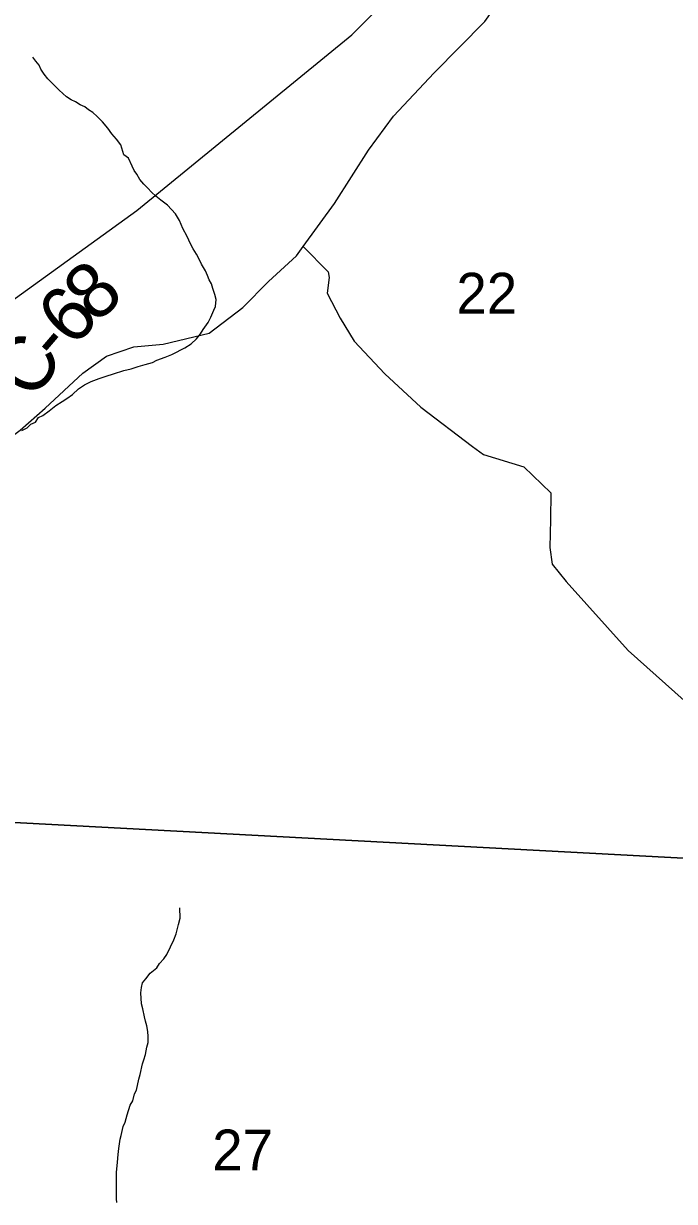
# Model space of a CAD drawing. Extents: x 0 to 34, y 0 to 22.
# Drawn here: x 5.915 to 6.583, y 16.581 to 17.789 of the extents above; entities that cross this region are included whole.
import ezdxf

# ---------------------------------------------------------------- set-up
doc = ezdxf.new("R2010")
doc.units = 0
for name, color, linetype in [('GM_P_State_Alignment', 7, 'Continuous'), ('GM_X_County_Road', 7, 'Continuous'), ('GM_X_County_Road_Text', 7, 'Continuous'), ('GM_X_Minor_River', 7, 'Continuous'), ('GM_X_Section', 7, 'Continuous'), ('GM_X_Section_Text', 7, 'Continuous'), ('GM_X_Township_ROW', 7, 'Continuous'), ('SH_Data', 7, 'Continuous')]:
    doc.layers.add(name, color=color, linetype=linetype)

msp = doc.modelspace()

# ---------------------------------------------------------------- linework, layer by layer
at = {"layer": 'GM_P_State_Alignment'}
msp.add_lwpolyline([(5.7539, 17.3702), (5.755, 17.3719), (5.7846, 17.4188), (6.0315, 17.5972), (6.2517, 17.7771), (6.3812, 17.906), (6.3923, 17.9142), (6.5211, 17.9881), (6.5265, 17.9911), (6.5405, 17.99), (6.6417, 17.9816), (6.6804, 17.9677), (6.7928, 17.9227), (6.8111, 17.9139), (6.95, 17.8445), (6.9564, 17.8413), (6.9734, 17.8302), (7.1338, 17.7232), (7.4175, 17.6454), (7.7316, 17.5623), (7.9253, 17.5014), (8.1533, 17.4614), (8.4655, 17.4165), (8.5004, 17.4073)], dxfattribs=at)
at = {"layer": 'GM_X_County_Road'}
msp.add_lwpolyline([(5.8626, 17.3148), (5.864, 17.3177), (5.8632, 17.3276), (5.8651, 17.3344), (5.8738, 17.3436), (5.9117, 17.3717), (5.9375, 17.3945), (5.9761, 17.4302), (6.0004, 17.4477), (6.0284, 17.4572), (6.0584, 17.4599), (6.1057, 17.4713), (6.1402, 17.4976), (6.1663, 17.5242), (6.1951, 17.5504), (6.2021, 17.56), (6.2341, 17.6043), (6.269, 17.659), (6.2947, 17.6936), (6.3364, 17.7381), (6.3883, 17.7909), (6.4224, 17.8395), (6.444, 17.868), (6.4684, 17.8891)], dxfattribs=at)
at = {"layer": 'GM_X_Minor_River'}
for points in [[(6.0016, 17.6814), (5.9961, 17.688), (5.9908, 17.6934), (5.9864, 17.6976), (5.9819, 17.7004), (5.9781, 17.7035), (5.9733, 17.7055), (5.9684, 17.7086), (5.9639, 17.7106), (5.9594, 17.7137), (5.9519, 17.7203), (5.9475, 17.7245), (5.94, 17.7322), (5.9363, 17.7369), (5.933, 17.7419), (5.9312, 17.7461), (5.9278, 17.7503), (5.9249, 17.7541)], [(5.9136, 17.3716), (5.919, 17.3742), (5.9228, 17.3779), (5.9274, 17.3801), (5.9305, 17.3846), (5.9351, 17.3868), (5.9416, 17.3917), (5.9485, 17.3969), (5.9547, 17.401), (5.9597, 17.4043), (5.9654, 17.4084), (5.9716, 17.414), (5.9777, 17.4184), (5.9846, 17.4217), (5.9926, 17.4246), (5.9998, 17.4272), (6.0074, 17.4297), (6.0181, 17.433), (6.0257, 17.4347), (6.0326, 17.4369), (6.0398, 17.4391), (6.0474, 17.4412), (6.052, 17.4434), (6.0604, 17.4467), (6.0673, 17.4492), (6.0722, 17.4518), (6.0764, 17.454), (6.0806, 17.4562), (6.0871, 17.4603), (6.0925, 17.4655), (6.0968, 17.4704), (6.0995, 17.4749), (6.1046, 17.4821), (6.1073, 17.4877), (6.1105, 17.4949), (6.1121, 17.4987), (6.1126, 17.5059), (6.1115, 17.5108), (6.1093, 17.517), (6.1079, 17.5219), (6.1057, 17.5258), (6.1039, 17.5304), (6.1017, 17.5353), (6.0977, 17.5419), (6.0955, 17.5465), (6.0925, 17.5522), (6.0892, 17.5576), (6.0863, 17.563), (6.083, 17.5702), (6.0786, 17.5787), (6.0753, 17.5867), (6.0709, 17.5936), (6.0627, 17.6025), (6.056, 17.6075), (6.0508, 17.6118), (6.0463, 17.6157), (6.0426, 17.6199), (6.0385, 17.6242), (6.0344, 17.6288), (6.0315, 17.6342), (6.0285, 17.638), (6.0267, 17.6426), (6.0227, 17.6507), (6.0182, 17.6542), (6.015, 17.6645), (6.0105, 17.6703), (6.0057, 17.6757), (6.0016, 17.6814)], [(6.0108, 16.5798), (6.0105, 16.5836), (6.0104, 16.5977), (6.0106, 16.6106), (6.0116, 16.6213), (6.0121, 16.6289), (6.0129, 16.6353), (6.0142, 16.6448), (6.0154, 16.6486), (6.0175, 16.6577), (6.0195, 16.6622), (6.0215, 16.6698), (6.0247, 16.6796), (6.0274, 16.6841), (6.0291, 16.6913), (6.031, 16.6951), (6.0335, 16.7061), (6.0347, 16.711), (6.0372, 16.722), (6.0384, 16.7262), (6.0404, 16.7315), (6.0416, 16.739), (6.0429, 16.744), (6.043, 16.75), (6.0427, 16.755), (6.0416, 16.7611), (6.0402, 16.7657), (6.0391, 16.7703), (6.0374, 16.7783), (6.036, 16.7836), (6.0354, 16.7947), (6.0363, 16.8004), (6.0371, 16.8049), (6.0406, 16.809), (6.0452, 16.815), (6.0518, 16.8203), (6.0545, 16.8248), (6.0591, 16.8296), (6.0622, 16.8341), (6.0658, 16.8421), (6.0693, 16.8492), (6.0717, 16.8553), (6.0741, 16.8647), (6.0758, 16.8712), (6.0756, 16.8818)]]:
    msp.add_lwpolyline(points, dxfattribs=at)
at = {"layer": 'GM_X_Section'}
msp.add_lwpolyline([(5.784, 17.9889), (6.8533, 17.9287), (6.7904, 16.9223), (5.726, 16.9791)], close=True, dxfattribs=at)
msp.add_lwpolyline([(5.726, 16.9791), (6.7904, 16.9223), (6.7682, 16.601), (6.755, 16.5938), (6.7273, 16.5816), (6.68, 16.5577)], dxfattribs=at)
at = {"layer": 'GM_X_Township_ROW'}
msp.add_lwpolyline([(6.2021, 17.56), (6.2277, 17.5343), (6.2285, 17.5283), (6.2265, 17.5123), (6.2397, 17.4866), (6.2541, 17.4629), (6.2857, 17.4295), (6.3226, 17.3954), (6.3755, 17.3551), (6.387, 17.3469), (6.4282, 17.3342), (6.4559, 17.3076), (6.4555, 17.2802), (6.4547, 17.2513), (6.4574, 17.2342), (6.4715, 17.2166), (6.5351, 17.146), (6.6531, 17.0404), (6.7536, 17.0209), (6.7741, 17.0166), (6.7839, 17.0124), (6.7902, 17.0069), (6.8013, 16.9946)], dxfattribs=at)
at = {"layer": 'SH_Data'}
msp.add_lwpolyline([(5.7846, 17.4188), (6.0315, 17.5972), (6.2517, 17.7771), (6.3812, 17.906), (6.5265, 17.9911), (6.6417, 17.9816), (6.7928, 17.9227), (6.95, 17.8445), (7.1338, 17.7232), (7.4175, 17.6454), (7.7316, 17.5623), (7.9253, 17.5014)], dxfattribs=at)

# ---------------------------------------------------------------- texts
at = {"layer": 'GM_X_County_Road_Text'}
for s, rotation, p in [('8', 42.8202, (5.9893, 17.4801)), ('6', 45.9858, (5.9656, 17.4555)), ('C', 57.4988, (5.9271, 17.4008)), ('-', 49.2844, (5.9509, 17.4385))]:
    msp.add_text(s, height=0.0568, rotation=rotation, dxfattribs=at).set_placement(p)
at = {"layer": 'GM_X_Section_Text'}
for s, p in [('22', (6.3591, 17.4913)), ('27', (6.1087, 16.6127))]:
    msp.add_text(s, height=0.04186, rotation=0, dxfattribs=at).set_placement(p)

doc.saveas('drawing.dxf')
